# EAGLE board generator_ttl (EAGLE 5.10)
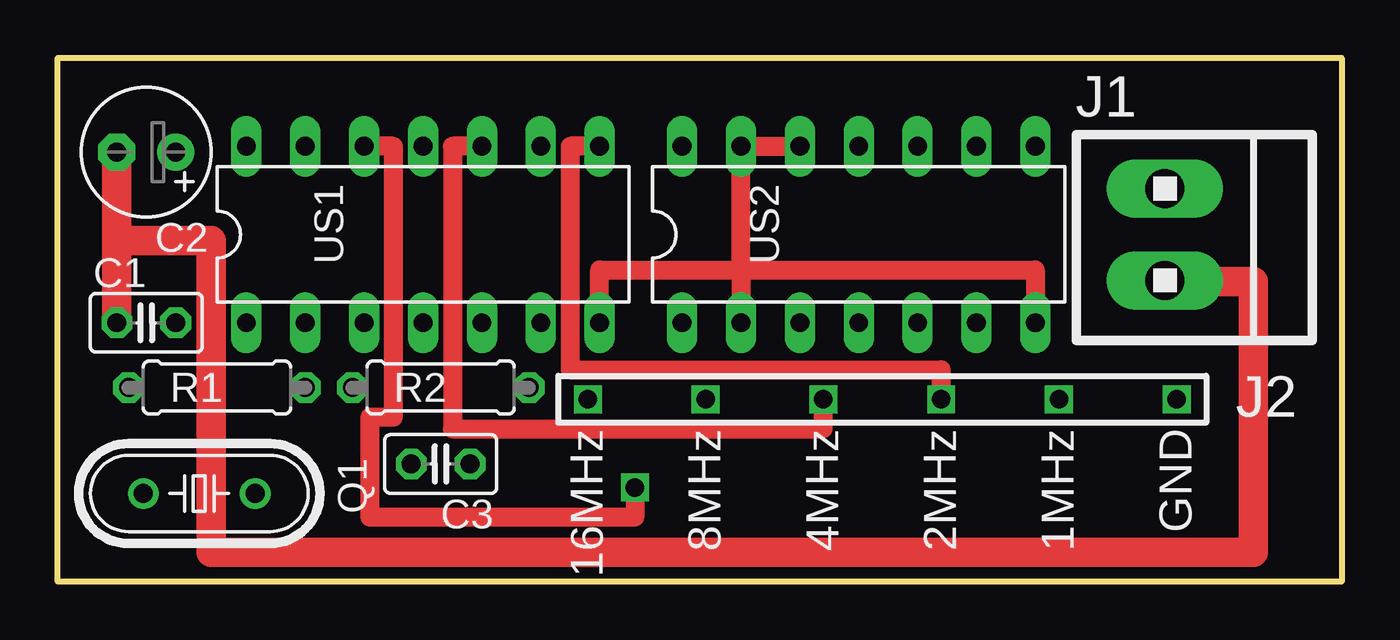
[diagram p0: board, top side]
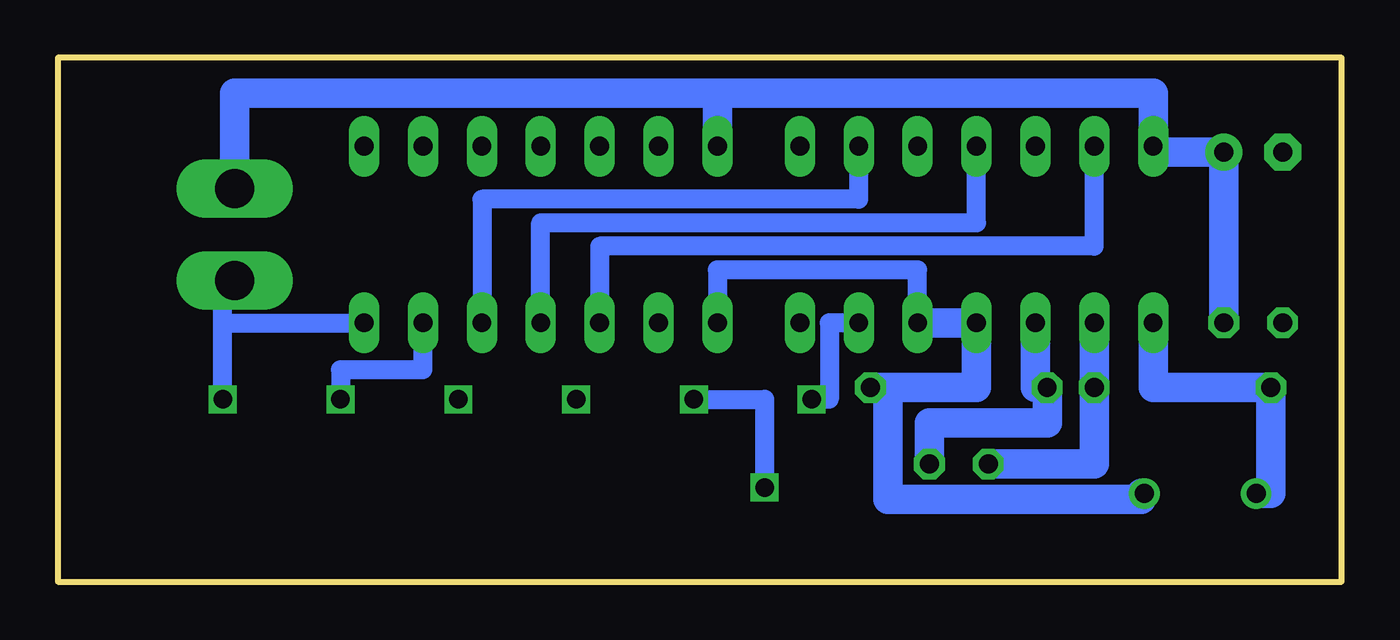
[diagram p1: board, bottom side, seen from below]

Size 55.37 x 22.61 mm. Coordinates in mm from the lower left corner, seen from the top.
Outline: 55.37,22.61 55.37,0 0,0 0,22.61 55.37,22.61
Copper layers (1*16): Top 0.035mm / dielectric 1.5mm / Bottom 0.035mm
Design rules "default": minimum track width 10mil, minimum drill 24mil, track to track 8mil, track to pad 8mil, pad to pad 8mil, via to via 8mil, smd to smd 8mil, copper to edge 40mil, drill to drill 8mil, minimum pad ring 10mil, minimum via ring 8mil, stop-mask expansion 4mil, vias tented up to drill 0mil, thermal gap 10mil

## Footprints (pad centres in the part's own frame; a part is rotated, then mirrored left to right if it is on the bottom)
C025-025X050 = drill 0.813 octagon: 1 -1.27,0; 2 1.27,0
E2,5-6 = drill 0.813 pad 1.6 round: + -1.27,0 | drill 0.813 pad 1.6 octagon: - 1.27,0
1X2MTA = drill 1.676 long: 1 1.981,0; 2 -1.981,0
HC49/S = drill 0.813 round: 1 -2.413,0; 2 2.413,0
0207/7 = drill 0.813 octagon: 1 -3.81,0; 2 3.81,0
DIL14 = drill 0.813 long: 1 -7.62,-3.81; 2 -5.08,-3.81; 3 -2.54,-3.81; 4 0,-3.81; 5 2.54,-3.81; 6 5.08,-3.81; 7 7.62,-3.81; 8 7.62,3.81; 9 5.08,3.81; 10 2.54,3.81; 11 0,3.81; 12 -2.54,3.81; 13 -5.08,3.81; 14 -7.62,3.81

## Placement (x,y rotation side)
C1  [C025-025X050]  3.81,11.18 0 top
C2  [E2,5-6]  3.81,18.54 180 top
C3  [C025-025X050]  16.51,5.08 180 top
J1  - +  [1X2MTA]  47.75,14.99 270 top
Q1  [HC49/S]  6.1,3.81 180 top
R1  [0207/7]  6.86,8.38 0 top
R2  [0207/7]  16.51,8.38 0 top
US1  [DIL14]  15.75,14.99 0 top
US2  [DIL14]  34.54,14.99 0 top

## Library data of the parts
C1-C3 R1 R2 = rcl
J1 = con-amp
Q1 = crystal
US1 US2 = 40xx

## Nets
S$1: R1.1 US1.1
S$2: C3.2 R1.2
S$4: US1.13
S$5: C3.1 R2.1 US1.3
S$6: US1.11
S$7: US1.9
S$9: R2.2 US1.5
S$10: US1.12
S$11: C1.2
S$13: C1.1 C2.-
S$16: US1.6
S$18: US1.10
S$19: US1.8

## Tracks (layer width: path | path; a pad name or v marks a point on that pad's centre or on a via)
S$1
  Bottom 1.27: US1.1 8.13,8.38 R1.1 3.05,3.81 3.56,3.81
S$2
  Bottom 1.27: 10.67,11.43 R1.2 10.67,5.08 C3.2
S$3
  Top 0.813: 42.16,11.18 42.16,13.46 29.46,13.46 | 32,18.8 29.46,18.8 29.46,13.46 | 29.46,13.46 29.46,11.18 | 29.46,13.46 23.37,13.46 23.37,11.43
S$4
  Bottom 0.813: 32,11.18 32,14.48 10.67,14.48 US1.13
S$5
  Bottom 1.27: C3.1 17.78,6.86 12.7,6.86 R2.1 13.21,8.38 US1.3
S$6
  Bottom 0.813: 34.54,11.43 34.54,15.49 15.75,15.49 US1.11
S$7
  Bottom 0.813: 37.08,11.18 37.08,16.51 20.83,16.51 US1.9
S$8  (via drill 0.8)
  Bottom 0.813: 48.26,11.18 42.16,11.18 | 48.26,11.18 48.26,12.7 | v48.26,7.87 48.26,11.18
S$9
  Bottom 0.813: 26.92,11.18 26.92,13.46 18.29,13.46 US1.5
  Bottom 1.27: 15.75,11.18 15.75,11.43 | 15.75,11.18 US1.5 | 15.75,11.18 15.75,8.38 19.56,8.38 | 19.56,8.38 R2.2 | 19.56,8.38 19.56,3.56 8.64,3.56 8.64,3.81
S$10  (via drill 0.8)
  Top 0.813: US1.12 14.48,18.8 14.48,7.11 13.46,7.11 13.46,2.79 24.89,2.79 v24.89,4.06
  Bottom 0.813: v27.94,7.87 24.89,7.87 v24.89,4.06
S$11
  Bottom 0.813: 47.75,17.02 47.75,16.76
  Bottom 1.27: C1.2 5.08,18.54 8.13,18.54 8.13,21.08 26.92,21.08 | 26.92,21.08 26.92,18.8 | 26.92,21.08 47.75,21.08 47.75,17.02
S$13
  Top 1.27: 2.54,14.73 C2.- | C1.1 2.54,14.73 | 47.75,12.95 51.56,12.95 51.56,1.27 6.6,1.27 6.6,14.73 2.54,14.73
S$15  (via drill 0.8)
  Bottom 0.813: 39.62,11.18 39.62,9.14 43.18,9.14 v43.18,7.87
S$16  (via drill 0.8)
  Bottom 0.813: US1.6 22.1,11.18 22.1,7.87 v22.86,7.87
S$18  (via drill 0.8)
  Top 0.813: US1.10 17.02,18.8 17.02,6.6 33.02,6.6 v33.02,7.87
S$19  (via drill 0.8)
  Top 0.813: US1.8 22.1,18.8 22.1,9.14 38.1,9.14 v38.1,7.87

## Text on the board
tNames: 16MHz | 8MHz | 4MHz | 2MHz | 1MHz | GND | J2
